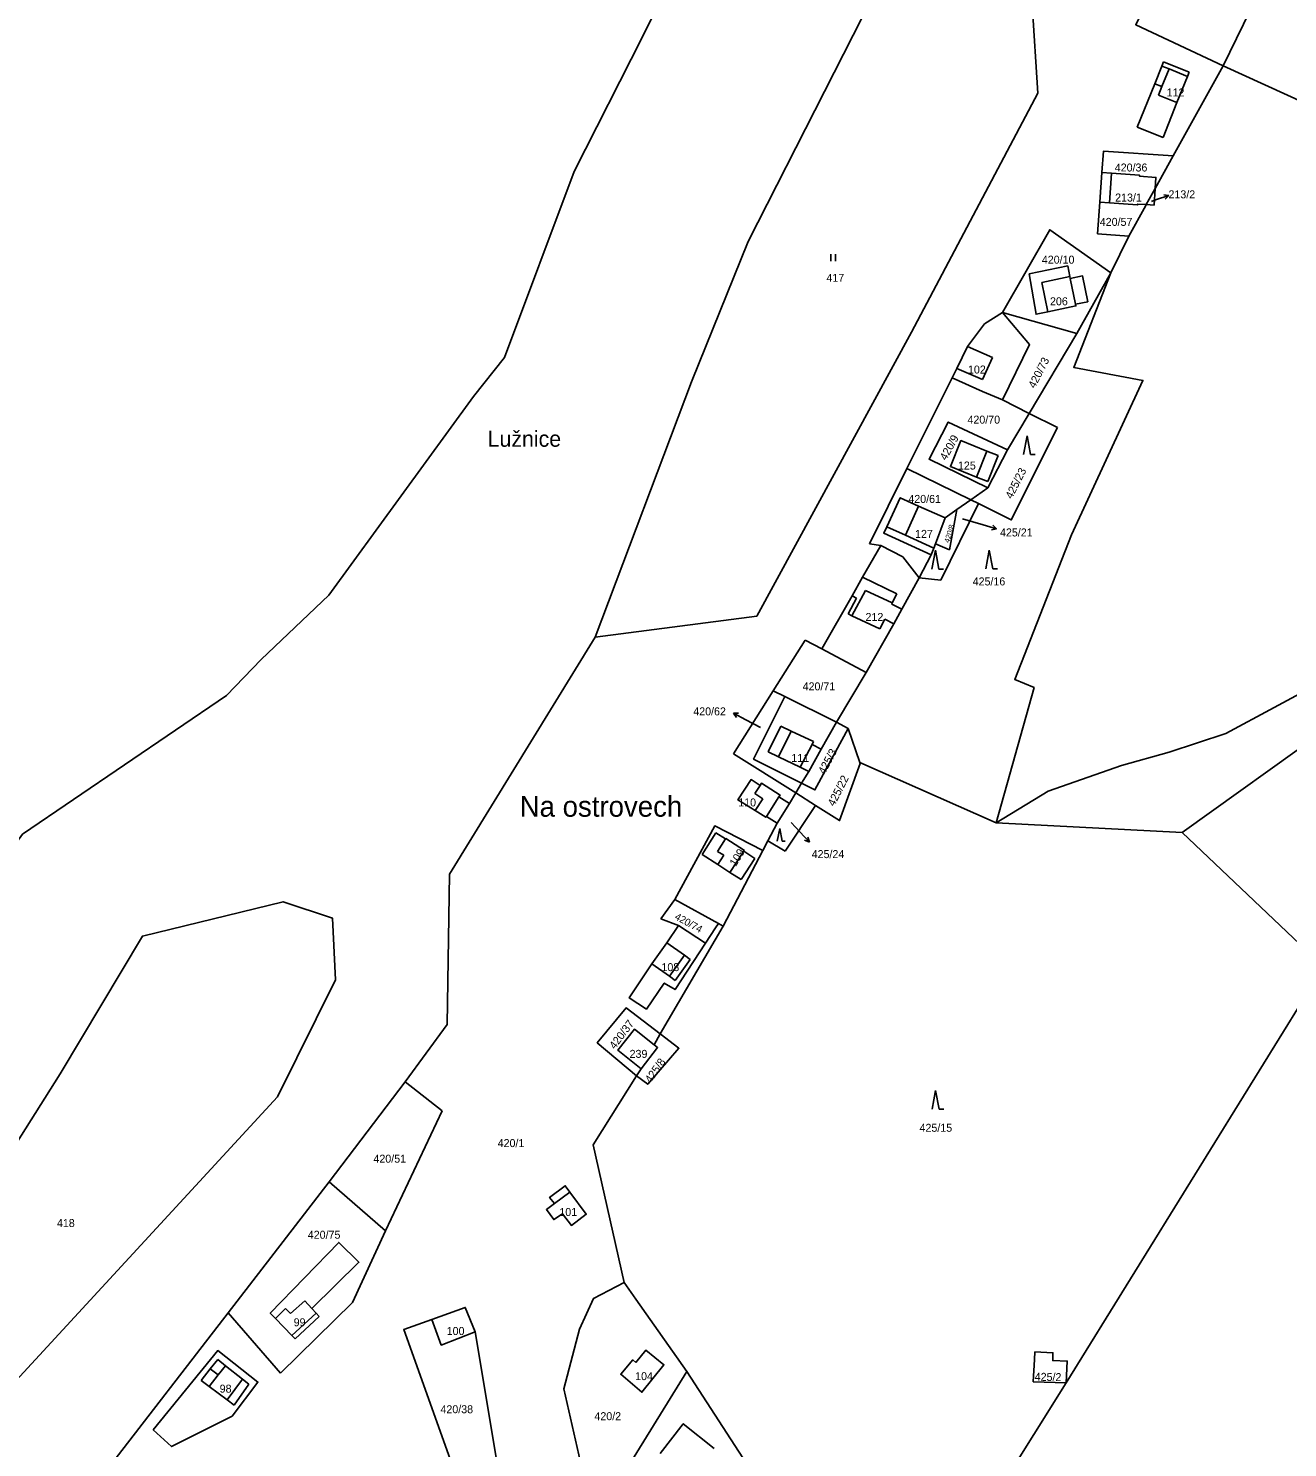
# Model space of a CAD drawing. Extents: x -751333 to -746055, y -1133395 to -1129777.
# Drawn here: x -748944.8 to -748676.3, y -1130426.4 to -1130123.8 of the extents above; entities that cross this region are included whole.
import ezdxf

# ---------------------------------------------------------------- set-up
doc = ezdxf.new("R2010")
doc.units = 0
for name, color, linetype in [('Hranice parcel', 7, 'Continuous'), ('Parcelní čísla', 7, 'Continuous'), ('Pop  PČ popisy', 7, 'Continuous'), ('Vnitřní kresba', 7, 'Continuous'), ('Značky kultur', 7, 'Continuous')]:
    doc.layers.add(name, color=color, linetype=linetype)

msp = doc.modelspace()

# ---------------------------------------------------------------- linework, layer by layer
at = {"layer": 'Hranice parcel'}
for p, q in [((-748679.01, -1130109.09), (-748690.03, -1130131.77)), ((-748697.25, -1130133.11), (-748702.73, -1130130.9)), ((-748700.69, -1130150.98), (-748690.03, -1130131.77)), ((-748708.33, -1130144.85), (-748702.84, -1130147.05)), ((-748704.51, -1130157.91), (-748700.69, -1130150.98)), ((-748716.32, -1130160.85), (-748715.86, -1130154.54)), ((-748706.41, -1130161.37), (-748704.51, -1130157.91)), ((-748714, -1130175.92), (-748710.11, -1130168.08)), ((-748721.25, -1130188.87), (-748714, -1130175.92)), ((-748737.09, -1130184.36), (-748721.25, -1130188.87)), ((-748721.25, -1130188.87), (-748731.36, -1130205.88)), ((-748757.48, -1130217.6), (-748747.82, -1130198.29)), ((-748731.36, -1130205.88), (-748737.1, -1130203.01)), ((-748735.98, -1130213.67), (-748731.36, -1130205.88)), ((-748731.36, -1130205.88), (-748725.34, -1130208.89)), ((-748740.23, -1130220.41), (-748738.01, -1130214.88)), ((-748740.17, -1130221.76), (-748735.98, -1130213.67)), ((-748765.43, -1130233.66), (-748757.48, -1130217.6)), ((-748743.82, -1130224.3), (-748757.48, -1130217.6)), ((-748743.82, -1130224.3), (-748740.17, -1130221.76)), ((-748742.19, -1130225.1), (-748750.19, -1130241.4)), ((-748746.82, -1130226.39), (-748743.82, -1130224.3)), ((-748742.19, -1130225.1), (-748743.82, -1130224.3)), ((-748751.33, -1130233.71), (-748749.28, -1130228.17)), ((-748746.82, -1130226.39), (-748749.28, -1130228.17)), ((-748762.98, -1130234.01), (-748765.43, -1130233.66)), ((-748754.82, -1130240.9), (-748752.26, -1130236.01)), ((-748750.19, -1130241.4), (-748754.82, -1130240.9)), ((-748785.95, -1130265.03), (-748779.14, -1130254.21)), ((-748779.14, -1130254.21), (-748775.58, -1130256.1)), ((-748775.58, -1130256.1), (-748766.14, -1130261.11)), ((-748766.14, -1130261.11), (-748772.5, -1130271.71)), ((-748794.41, -1130278.46), (-748785.95, -1130265.03)), ((-748783.49, -1130266.25), (-748785.95, -1130265.03)), ((-748772.5, -1130271.71), (-748783.49, -1130266.25)), ((-748769.96, -1130273.07), (-748772.5, -1130271.71)), ((-748769.96, -1130273.07), (-748767.48, -1130280.32)), ((-748781.17, -1130286.79), (-748794.41, -1130278.46)), ((-748738.44, -1130293.13), (-748767.48, -1130280.32)), ((-748767.48, -1130280.32), (-748767.41, -1130280.54)), ((-748781.17, -1130286.79), (-748779.93, -1130284.72)), ((-748782.51, -1130289.02), (-748781.17, -1130286.79)), ((-748781.17, -1130286.79), (-748776.93, -1130289.46)), ((-748785.13, -1130293.23), (-748782.51, -1130289.02)), ((-748776.93, -1130289.46), (-748783.4, -1130299.2)), ((-748787.12, -1130297.03), (-748785.13, -1130293.23)), ((-748698.75, -1130295.21), (-748738.44, -1130293.13)), ((-748788.18, -1130299.06), (-748787.12, -1130297.03)), ((-748783.4, -1130299.2), (-748787.12, -1130297.03)), ((-748668.63, -1130323.88), (-748698.75, -1130295.21)), ((-748796.64, -1130315.17), (-748788.18, -1130299.06)), ((-748809.94, -1130313.62), (-748806.96, -1130309.5)), ((-748806.96, -1130309.5), (-748797.65, -1130314.62)), ((-748810.09, -1130338.15), (-748796.64, -1130315.17)), ((-748806.14, -1130315.03), (-748809.94, -1130313.62)), ((-748800.38, -1130318.82), (-748806.14, -1130315.03)), ((-748797.65, -1130314.62), (-748796.64, -1130315.17)), ((-748811.31, -1130340.5), (-748810.09, -1130338.15)), ((-748815.11, -1130347.07), (-748814.15, -1130345.6)), ((-748864.43, -1130348.37), (-748880.65, -1130369.7)), ((-748864.43, -1130348.37), (-748856.57, -1130354.58)), ((-748856.57, -1130354.58), (-748868.66, -1130380.11)), ((-748902.2, -1130397.64), (-748880.65, -1130369.7)), ((-748880.65, -1130369.7), (-748868.66, -1130380.11)), ((-748902.2, -1130397.64), (-748927.95, -1130431.02)), ((-748891.04, -1130410.51), (-748902.2, -1130397.64)), ((-748887.91, -1130403.18), (-748882.74, -1130398.42)), ((-748849.48, -1130401.7), (-748844.76, -1130430.14)), ((-748819.51, -1130434.58), (-748804.37, -1130410.14)), ((-748792.44, -1130428.53), (-748804.37, -1130410.14))]:
    msp.add_line(p, q, dxfattribs=at)
for points in [[(-748769.65, -1130027.77), (-748783.5, -1130064.22), (-748813.85, -1130125.61), (-748828.39, -1130154.34), (-748843.29, -1130193.93), (-748849.85, -1130202.28), (-748880.72, -1130244.6), (-748895.14, -1130258.31), (-748902.53, -1130266.04), (-748946.04, -1130295.61), (-748968.51, -1130326.73), (-748986.86, -1130352.14), (-749004.75, -1130374.8), (-749024.24, -1130390.9), (-749046.5, -1130403.57), (-749076.25, -1130410.73)], [(-748690.03, -1130131.77), (-748708.67, -1130123.04), (-748703.2, -1130111.36), (-748695.73, -1130100.54)], [(-748758.78, -1130105.24), (-748791.3, -1130169.26), (-748803.39, -1130199.17), (-748823.92, -1130253.6)], [(-748823.92, -1130253.6), (-748789.46, -1130249.07), (-748756.47, -1130188.54), (-748729.51, -1130137.61), (-748730.72, -1130118.71)], [(-748702.73, -1130130.9), (-748703.1, -1130131.83), (-748704.61, -1130135.59), (-748708.33, -1130144.85)], [(-748702.84, -1130147.05), (-748699.88, -1130139.6), (-748697.62, -1130134.04), (-748697.25, -1130133.11)], [(-748690.03, -1130131.77), (-748628.64, -1130159.81), (-748623.71, -1130149.3)], [(-748715.86, -1130154.54), (-748715.53, -1130149.95), (-748700.69, -1130150.98)], [(-748715.86, -1130154.54), (-748713.83, -1130154.69), (-748707.83, -1130155.12), (-748707.84, -1130155.32), (-748704.35, -1130155.56), (-748704.51, -1130157.91)], [(-748704.51, -1130157.91), (-748704.74, -1130161.48), (-748706.41, -1130161.37)], [(-748710.11, -1130168.08), (-748716.81, -1130167.59), (-748716.32, -1130160.85)], [(-748706.41, -1130161.37), (-748708.24, -1130161.24), (-748708.25, -1130161.44), (-748714.25, -1130161), (-748716.32, -1130160.85)], [(-748710.11, -1130168.08), (-748706.52, -1130161.56), (-748706.41, -1130161.37)], [(-748737.09, -1130184.36), (-748726.98, -1130166.73), (-748714, -1130175.92)], [(-748738.44, -1130293.13), (-748730.34, -1130264.28), (-748734.46, -1130262.58), (-748722.39, -1130231.8), (-748707.13, -1130198.83), (-748721.89, -1130196.08), (-748714, -1130175.92)], [(-748731.39, -1130176.15), (-748729.92, -1130184.74), (-748727.41, -1130184.22), (-748721.4, -1130182.98), (-748721.47, -1130182.61), (-748718.88, -1130182.08), (-748720.01, -1130176.57), (-748722.61, -1130177.15), (-748722.7, -1130176.69), (-748723.16, -1130174.45), (-748731.39, -1130176.15)], [(-748737.09, -1130184.36), (-748740.9, -1130186.8), (-748744.52, -1130191.64), (-748746.84, -1130196.34), (-748747.82, -1130198.29)], [(-748737.1, -1130203.01), (-748731.34, -1130191.16), (-748737.09, -1130184.36)], [(-748747.82, -1130198.29), (-748741.36, -1130201.22), (-748737.1, -1130203.01)], [(-748735.98, -1130213.67), (-748748.65, -1130207.73), (-748752.73, -1130215.64), (-748740.17, -1130221.76)], [(-748725.34, -1130208.89), (-748735.2, -1130228.6), (-748742.19, -1130225.1)], [(-748738.01, -1130214.88), (-748740.38, -1130213.93), (-748745.94, -1130211.69), (-748748.16, -1130217.21), (-748742.6, -1130219.46), (-748740.23, -1130220.41)], [(-748749.28, -1130228.17), (-748754.98, -1130225.64), (-748758.89, -1130223.86), (-748761.74, -1130230.08), (-748762.39, -1130231.38), (-748752.26, -1130236.01)], [(-748751.33, -1130233.71), (-748748.4, -1130234.96), (-748746.82, -1130226.39)], [(-748762.98, -1130234.01), (-748766.91, -1130240.77), (-748769.14, -1130244.76), (-748775.58, -1130256.1)], [(-748754.82, -1130240.9), (-748758.32, -1130236.48), (-748762.98, -1130234.01)], [(-748752.26, -1130236.01), (-748751.69, -1130234.6), (-748751.33, -1130233.71)], [(-748619.86, -1130238.05), (-748630.7, -1130232.75), (-748645.83, -1130254.45), (-748668.82, -1130263), (-748689.45, -1130274.13), (-748701.54, -1130278.1), (-748711.73, -1130280.94), (-748727.3, -1130286.44), (-748738.44, -1130293.13)], [(-748766.14, -1130261.11), (-748760.24, -1130250.76), (-748758.55, -1130247.6), (-748754.82, -1130240.9)], [(-748823.92, -1130253.6), (-748854.96, -1130304.08), (-748855.51, -1130336.17), (-748864.43, -1130348.37)], [(-748783.49, -1130266.25), (-748790.13, -1130279.57), (-748779.93, -1130284.72)], [(-748779.93, -1130284.72), (-748778.37, -1130282.24), (-748775.74, -1130277.43), (-748772.5, -1130271.71)], [(-748779.93, -1130284.72), (-748777.08, -1130286.16), (-748772.66, -1130278.04), (-748769.96, -1130273.07)], [(-748660.62, -1130279.14), (-748667.98, -1130273.2), (-748698.75, -1130295.21)], [(-748767.41, -1130280.54), (-748771.8, -1130292.68), (-748776.93, -1130289.46)], [(-748782.51, -1130289.02), (-748784.73, -1130287.64), (-748784.5, -1130287.26), (-748788.46, -1130284.72), (-748788.75, -1130285.18), (-748790.68, -1130283.93), (-748793.48, -1130288.27), (-748789.82, -1130290.55), (-748787.52, -1130291.98), (-748787.42, -1130291.81), (-748785.13, -1130293.23)], [(-748788.18, -1130299.06), (-748798.43, -1130293.81), (-748806.96, -1130309.5)], [(-748949.52, -1130364.94), (-748986.71, -1130413.35), (-749021.18, -1130438.69), (-749039.34, -1130444.89), (-748979.86, -1130434.67), (-748949.09, -1130413.89), (-748891.67, -1130351.56), (-748879.27, -1130326.65), (-748879.92, -1130313.49), (-748890.47, -1130310), (-748920.48, -1130317.29), (-748937.99, -1130346.67), (-748949.52, -1130364.94)], [(-748806.14, -1130315.03), (-748808.63, -1130318.75), (-748811.81, -1130323.23), (-748816.64, -1130330.48), (-748813.01, -1130332.88), (-748809.18, -1130327.32), (-748806.88, -1130328.7), (-748800.38, -1130318.82)], [(-748797.65, -1130314.62), (-748798.26, -1130315.56), (-748800.38, -1130318.82)], [(-748668.63, -1130323.88), (-748723.49, -1130412.55), (-748757.6, -1130467.05)], [(-748815.11, -1130347.07), (-748823.47, -1130340.04), (-748817.34, -1130332.61), (-748810.09, -1130338.15)], [(-748811.31, -1130340.5), (-748815.51, -1130337.13), (-748819.07, -1130341.63), (-748814.15, -1130345.6)], [(-748815.11, -1130347.07), (-748812.71, -1130348.9), (-748806.07, -1130341.2), (-748810.09, -1130338.15)], [(-748814.15, -1130345.6), (-748810.6, -1130341.06), (-748811.31, -1130340.5)], [(-748817.71, -1130391.16), (-748824.37, -1130361.8), (-748815.11, -1130347.07)], [(-748830.87, -1130376.52), (-748828.98, -1130378.98), (-748825.82, -1130376.61), (-748829.31, -1130371.87), (-748830.3, -1130370.53), (-748833.64, -1130373.02), (-748832.62, -1130374.32), (-748834.33, -1130375.61), (-748832.74, -1130377.75), (-748830.87, -1130376.52)], [(-748882.74, -1130398.42), (-748883.42, -1130397.69), (-748884.35, -1130396.68), (-748874.31, -1130386.85), (-748878.59, -1130382.61), (-748893.2, -1130397.67), (-748892.12, -1130398.79), (-748888.59, -1130402.45), (-748887.91, -1130403.18)], [(-748868.66, -1130380.11), (-748875.66, -1130395.41), (-748891.04, -1130410.51)], [(-748825.64, -1130435.7), (-748830.6, -1130413.85), (-748827.29, -1130401.09), (-748824.29, -1130394.55), (-748817.71, -1130391.16)], [(-748804.37, -1130410.14), (-748815.28, -1130394.69), (-748817.71, -1130391.16)], [(-748849.48, -1130401.7), (-748851.62, -1130396.45), (-748858.73, -1130399.01)], [(-748852.71, -1130434.75), (-748864.73, -1130401.17), (-748858.73, -1130399.01)], [(-748858.73, -1130399.01), (-748856.73, -1130404.51), (-748849.48, -1130401.7)], [(-748918.2, -1130422.56), (-748914.26, -1130426.13), (-748901.34, -1130419.64), (-748895.85, -1130412.39), (-748904.4, -1130405.67), (-748918.2, -1130422.56)], [(-748815.24, -1130408.18), (-748815.91, -1130407.67), (-748818.48, -1130410.72), (-748813.94, -1130414.55), (-748809.28, -1130408.69), (-748813.12, -1130405.56), (-748815.24, -1130408.18)], [(-748730.17, -1130405.92), (-748730.26, -1130407.59), (-748730.51, -1130412.32), (-748723.49, -1130412.55), (-748723.25, -1130407.92), (-748726.36, -1130407.78), (-748726.31, -1130406.11), (-748730.17, -1130405.92)], [(-748798.53, -1130426.57), (-748805.14, -1130421.28), (-748810.06, -1130427.6)]]:
    msp.add_lwpolyline(points, dxfattribs=at)
at = {"layer": 'Pop  PČ popisy'}
for p, q in [((-748705.32, -1130160.69), (-748704.43, -1130160.38)), ((-748704.43, -1130160.38), (-748701.593, -1130159.403)), ((-748701.593, -1130159.403), (-748702.702, -1130159.256)), ((-748701.593, -1130159.403), (-748702.376, -1130160.202)), ((-748745.61, -1130228.38), (-748741.21, -1130229.65)), ((-748741.21, -1130229.65), (-748738.325, -1130230.477)), ((-748738.325, -1130230.477), (-748739.426, -1130230.682)), ((-748738.325, -1130230.477), (-748739.15, -1130229.72)), ((-748791.8, -1130271.18), (-748794.45, -1130269.771)), ((-748794.45, -1130269.771), (-748793.33, -1130269.799)), ((-748794.45, -1130269.771), (-748793.801, -1130270.683)), ((-748788.66, -1130272.87), (-748791.8, -1130271.18)), ((-748782.11, -1130293.1), (-748780.3, -1130295.07)), ((-748780.3, -1130295.07), (-748778.253, -1130297.265)), ((-748778.253, -1130297.265), (-748779.303, -1130296.874)), ((-748778.253, -1130297.265), (-748778.57, -1130296.191))]:
    msp.add_line(p, q, dxfattribs=at)
at = {"layer": 'Vnitřní kresba'}
for p, q in [((-748701.56, -1130132.45), (-748703.1, -1130131.83)), ((-748701.56, -1130132.45), (-748703.07, -1130136.19)), ((-748697.62, -1130134.04), (-748701.56, -1130132.45)), ((-748703.07, -1130136.19), (-748704.61, -1130135.59)), ((-748703.81, -1130138.03), (-748703.07, -1130136.19)), ((-748699.88, -1130139.6), (-748703.81, -1130138.03)), ((-748713.83, -1130154.69), (-748714.25, -1130161)), ((-748728.7, -1130178), (-748722.7, -1130176.69)), ((-748728.7, -1130178), (-748727.41, -1130184.22)), ((-748722.61, -1130177.15), (-748721.47, -1130182.61)), ((-748744.52, -1130191.64), (-748739.2, -1130193.97)), ((-748739.2, -1130193.97), (-748741.36, -1130198.67)), ((-748741.36, -1130198.67), (-748746.84, -1130196.34)), ((-748740.38, -1130213.93), (-748742.6, -1130219.46)), ((-748754.98, -1130225.64), (-748757.76, -1130231.87)), ((-748761.74, -1130230.08), (-748757.76, -1130231.87)), ((-748757.76, -1130231.87), (-748751.69, -1130234.6)), ((-748766.91, -1130240.77), (-748759.59, -1130244.35)), ((-748769.98, -1130248.6), (-748768.19, -1130245.29)), ((-748769.23, -1130249), (-748766.3, -1130243.62)), ((-748768.19, -1130245.29), (-748769.14, -1130244.76)), ((-748760.57, -1130246.28), (-748766.3, -1130243.62)), ((-748760.57, -1130246.28), (-748760.7, -1130246.53)), ((-748759.59, -1130244.35), (-748760.57, -1130246.28)), ((-748769.23, -1130249), (-748769.98, -1130248.6)), ((-748769.23, -1130249), (-748763.24, -1130251.82)), ((-748760.7, -1130246.53), (-748758.55, -1130247.6)), ((-748763.24, -1130251.82), (-748762.13, -1130249.77)), ((-748762.13, -1130249.77), (-748760.24, -1130250.76)), ((-748784.36, -1130272.57), (-748787.03, -1130277.99)), ((-748782.13, -1130273.6), (-748784.84, -1130279.06)), ((-748784.36, -1130272.57), (-748782.13, -1130273.6)), ((-748782.13, -1130273.6), (-748777.35, -1130275.8)), ((-748777.66, -1130276.43), (-748780.2, -1130281.31)), ((-748777.35, -1130275.8), (-748777.66, -1130276.43)), ((-748777.66, -1130276.43), (-748775.74, -1130277.43)), ((-748787.03, -1130277.99), (-748784.84, -1130279.06)), ((-748784.84, -1130279.06), (-748780.2, -1130281.31)), ((-748780.2, -1130281.31), (-748778.37, -1130282.24)), ((-748789.9, -1130286.91), (-748788.75, -1130285.18)), ((-748788.2, -1130288.01), (-748789.9, -1130286.91)), ((-748788.2, -1130288.01), (-748789.82, -1130290.55)), ((-748784.73, -1130287.64), (-748787.42, -1130291.81)), ((-748801.13, -1130299.89), (-748798.19, -1130295.26)), ((-748798.19, -1130295.26), (-748796.14, -1130296.6)), ((-748797.81, -1130299.24), (-748796.14, -1130296.6)), ((-748796.14, -1130296.6), (-748796.06, -1130296.47)), ((-748796.06, -1130296.47), (-748792.1, -1130299.05)), ((-748801.13, -1130299.89), (-748797.8, -1130302.06)), ((-748796.51, -1130300.08), (-748797.81, -1130299.24)), ((-748796.51, -1130300.08), (-748797.8, -1130302.06)), ((-748792.21, -1130299.21), (-748795.2, -1130303.75)), ((-748789.87, -1130300.75), (-748792.77, -1130305.21)), ((-748792.1, -1130299.05), (-748792.21, -1130299.21)), ((-748792.21, -1130299.21), (-748789.87, -1130300.75)), ((-748797.8, -1130302.06), (-748795.2, -1130303.75)), ((-748792.77, -1130305.21), (-748795.2, -1130303.75)), ((-748808.63, -1130318.75), (-748804.89, -1130321.4)), ((-748804.89, -1130321.4), (-748808.08, -1130325.85)), ((-748804.89, -1130321.4), (-748803.64, -1130322.29)), ((-748808.08, -1130325.85), (-748811.81, -1130323.23)), ((-748803.64, -1130322.29), (-748806.86, -1130326.76)), ((-748806.86, -1130326.76), (-748808.08, -1130325.85)), ((-748832.62, -1130374.32), (-748829.31, -1130371.87)), ((-748889.92, -1130396.67), (-748892.12, -1130398.79)), ((-748888.89, -1130397.74), (-748889.92, -1130396.67)), ((-748885.85, -1130395.05), (-748888.89, -1130397.74)), ((-748883.42, -1130397.69), (-748888.59, -1130402.45)), ((-748884.35, -1130396.68), (-748885.85, -1130395.05)), ((-748905.99, -1130409.58), (-748907.94, -1130412.06)), ((-748904.4, -1130407.58), (-748905.99, -1130409.58)), ((-748905.99, -1130409.58), (-748904.29, -1130410.87)), ((-748902.74, -1130408.89), (-748904.4, -1130407.58)), ((-748902.74, -1130408.89), (-748904.29, -1130410.87)), ((-748899.09, -1130411.79), (-748902.74, -1130408.89)), ((-748907.94, -1130412.06), (-748906.24, -1130413.33)), ((-748904.29, -1130410.87), (-748906.24, -1130413.33)), ((-748899.09, -1130411.79), (-748902.41, -1130416.18)), ((-748900.92, -1130417.27), (-748897.75, -1130412.85)), ((-748897.75, -1130412.85), (-748899.09, -1130411.79)), ((-748906.24, -1130413.33), (-748902.41, -1130416.18)), ((-748902.41, -1130416.18), (-748900.92, -1130417.27))]:
    msp.add_line(p, q, dxfattribs=at)
at = {"layer": 'Značky kultur'}
for p, q in [((-748773.651, -1130173.46), (-748773.651, -1130171.96)), ((-748772.65, -1130173.46), (-748772.65, -1130171.96)), ((-748731.82, -1130210.65), (-748732.57, -1130214.65)), ((-748731.07, -1130214.65), (-748731.82, -1130210.65)), ((-748731.07, -1130214.65), (-748730.074, -1130214.65)), ((-748751.37, -1130235.05), (-748752.12, -1130239.05)), ((-748750.62, -1130239.05), (-748751.37, -1130235.05)), ((-748739.9, -1130235), (-748740.65, -1130239)), ((-748739.15, -1130239), (-748739.9, -1130235)), ((-748750.62, -1130239.05), (-748749.624, -1130239.05)), ((-748739.15, -1130239), (-748738.154, -1130239)), ((-748784.58, -1130294.37), (-748785.082, -1130297.05)), ((-748784.078, -1130297.05), (-748784.58, -1130294.37)), ((-748784.078, -1130297.05), (-748783.41, -1130297.05)), ((-748751.33, -1130350.23), (-748752.08, -1130354.23)), ((-748750.58, -1130354.23), (-748751.33, -1130350.23)), ((-748750.58, -1130354.23), (-748749.584, -1130354.23))]:
    msp.add_line(p, q, dxfattribs=at)

# ---------------------------------------------------------------- texts
at = {"layer": 'Parcelní čísla'}
for s, p in [('112', (-748702.07, -1130138.31)), ('420/36', (-748713.13, -1130154.31)), ('213/2', (-748701.678, -1130160.03)), ('213/1', (-748713.048, -1130160.71)), ('420/57', (-748716.327, -1130165.9)), ('420/10', (-748728.68, -1130173.96)), ('417', (-748774.61, -1130177.83)), ('206', (-748726.94, -1130182.83)), ('102', (-748744.43, -1130197.38)), ('420/70', (-748744.537, -1130208.06)), ('125', (-748746.565, -1130217.84)), ('420/61', (-748757.147, -1130224.96)), ('127', (-748755.71, -1130232.41)), ('425/21', (-748737.6, -1130232.104)), ('425/16', (-748743.43, -1130242.55)), ('212', (-748766.28, -1130250.13)), ('420/71', (-748779.687, -1130264.92)), ('420/62', (-748803.005, -1130270.25)), ('111', (-748782.1, -1130280.19)), ('110', (-748793.415, -1130289.66)), ('425/24', (-748777.76, -1130300.678)), ('108', (-748809.79, -1130324.77)), ('239', (-748816.58, -1130343.26)), ('425/15', (-748754.76, -1130359.02)), ('420/1', (-748844.71, -1130362.28)), ('420/51', (-748871.2, -1130365.61)), ('101', (-748831.56, -1130376.98)), ('418', (-748938.69, -1130379.33)), ('420/75', (-748885.2, -1130381.82)), ('99', (-748888.21, -1130400.48)), ('100', (-748855.58, -1130402.34)), ('104', (-748815.4, -1130411.97)), ('98', (-748903.99, -1130414.63)), ('420/38', (-748856.91, -1130419.02)), ('420/2', (-748824.08, -1130420.5))]:
    msp.add_text(s, height=1.7, dxfattribs=at).set_placement(p)
for s, height, rotation, p in [('420/73', 1.7, 63, (-748730.174, -1130200.673)), ('420/9', 1.7, 61, (-748749.086, -1130216.042)), ('425/23', 1.7, 63, (-748735.064, -1130224.233)), ('420/8', 1.14, 73, (-748748.451, -1130233.551)), ('425/3', 1.7, 62, (-748774.979, -1130282.949)), ('425/22', 1.7, 63, (-748772.944, -1130289.783)), ('109', 1.7, 58, (-748793.959, -1130302.59)), ('420/74', 1.535, 331, (-748807.099, -1130313.623)), ('420/37', 1.7, 53, (-748819.721, -1130341.551)), ('425/8', 1.7, 55, (-748812.083, -1130348.767)), ('425/2', 1.7, 359, (-748730.212, -1130412.082))]:
    msp.add_text(s, height=height, rotation=rotation, dxfattribs=at).set_placement(p)
at = {"layer": 'Pop  PČ popisy'}
for s, height, p in [('Lužnice', 3.4, (-748846.856, -1130212.99)), ('Na ostrovech', 4.4, (-748840.019, -1130291.86))]:
    msp.add_text(s, height=height, dxfattribs=at).set_placement(p)

doc.saveas('drawing.dxf')
